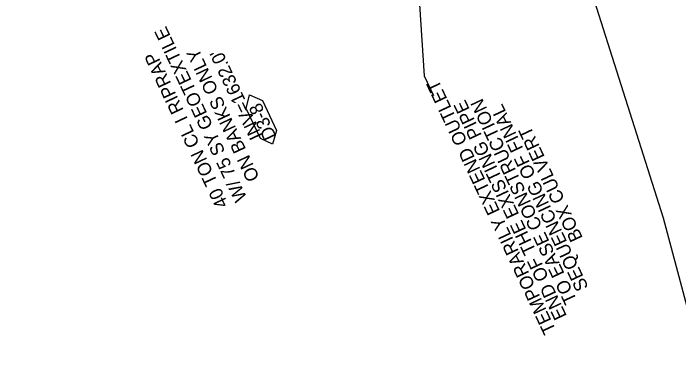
# Model space of a CAD drawing. Extents: x 465700 to 483515, y 488970 to 507540.
# Drawn here: x 477587 to 477838.2, y 499135.1 to 499267.5 of the extents above; entities that cross this region are included whole.
import ezdxf

# ---------------------------------------------------------------- set-up
doc = ezdxf.new("R2010")
doc.units = 0
for name, color, linetype in [('Exist Plan Preparation Watershed Blue', 7, 'Continuous'), ('Prop Drainage Structure Box Number Symbol CELL', 7, 'Continuous'), ('Prop Drainage Structure Tops and Inverts LABEL', 7, 'Continuous'), ('Prop Erosion Rip Rap Pad at Outlet Label', 7, 'Continuous')]:
    doc.layers.add(name, color=color, linetype=linetype)

msp = doc.modelspace()

# ---------------------------------------------------------------- linework, layer by layer
at = {"layer": 'Exist Plan Preparation Watershed Blue'}
msp.add_lwpolyline([(477858.24, 499093.41), (477832.51, 499190.03), (477802.27, 499285.34), (477767.58, 499379.12), (477747.49, 499427.65), (477728.52, 499471.17), (477710.77, 499509.04), (477685.16, 499561.27), (477643.08, 499639.33), (477611.01, 499694.79), (477581.24, 499742.27)], dxfattribs=at)
at = {"layer": 'Prop Drainage Structure Box Number Symbol CELL'}
msp.add_lwpolyline([(477680.3, 499220.13), (477674.91, 499231.53), (477676.08, 499236.62), (477681, 499234.58), (477686.39, 499223.19), (477684.86, 499218.04), (477680.3, 499220.13)], dxfattribs=at)
at = {"layer": 'Prop Erosion Rip Rap Pad at Outlet Label'}
msp.add_lwpolyline([(477737.73, 499311.38), (477742.06, 499243.89), (477745.57, 499236.47)], dxfattribs=at)

# ---------------------------------------------------------------- texts
at = {"layer": 'Prop Drainage Structure Box Number Symbol CELL'}
msp.add_text('D3-8', height=5, rotation=115.2909, dxfattribs=at).set_placement((477686.42, 499220.97))
at = {"layer": 'Prop Drainage Structure Tops and Inverts LABEL'}
msp.add_text("INV=1632.0'", height=5, rotation=115.2938, dxfattribs=at).set_placement((477681.14, 499221.12))
at = {"layer": 'Prop Erosion Rip Rap Pad at Outlet Label'}
for s, rotation, p in [('W/ 75 SY GEOTEXTILE', 115.2938, (477675.35, 499197.72)), ('40 TON CL I RIPRAP', 115.2938, (477668.22, 499195.25)), ('ON BANKS ONLY', 115.2938, (477680.03, 499205.35)), ('TEMPORARILY EXTEND OUTLET', 115.1706, (477792.01, 499147.69)), ('END OF THE EXISTING PIPE', 115.1706, (477796.08, 499153.13)), ('TO EASE CONSTRUCTION', 115.1706, (477799.94, 499159.03)), ('SEQUENCING OF FINAL ', 115.1706, (477804.25, 499163.97)), ('BOX CULVERT', 115.1706, (477802.11, 499182.62))]:
    msp.add_text(s, height=5, rotation=rotation, dxfattribs=at).set_placement(p)

doc.saveas('drawing.dxf')
